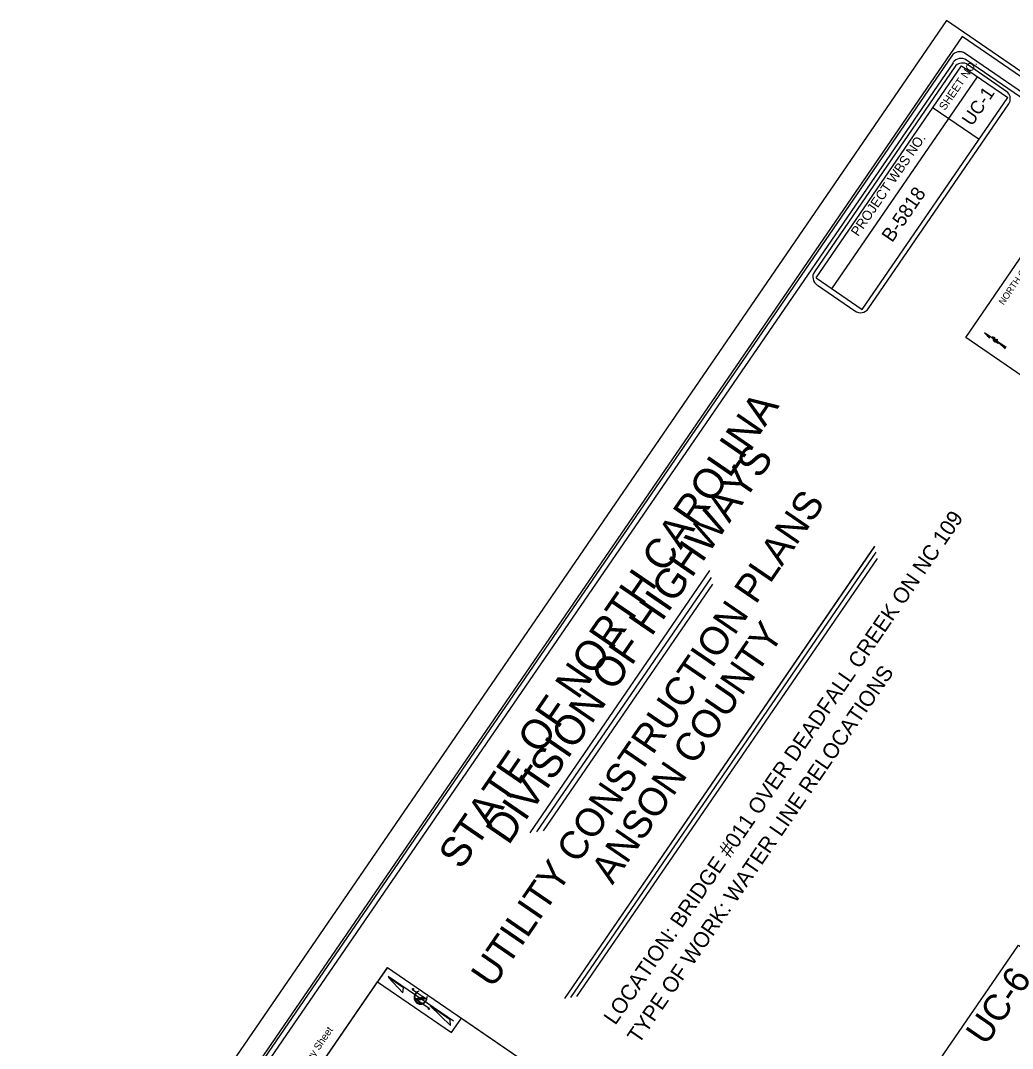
# Model space of a CAD drawing. Extents: x 1638787 to 1643250, y 391480 to 396306.
# Drawn here: x 1638787 to 1641236, y 393769 to 396306 of the extents above; entities that cross this region are included whole.
import ezdxf

# ---------------------------------------------------------------- set-up
doc = ezdxf.new("R2010")
doc.units = 0
for name, color, linetype in [('Old_Level_1', 7, 'Continuous'), ('Old_Level_32', 7, 'Continuous'), ('Old_Level_5', 7, 'Continuous'), ('Sheet North Arrow CELL', 7, 'Continuous'), ('Sheet Plan Layout CELL', 7, 'Continuous'), ('Sheet Plot Border Inside CELL', 7, 'Continuous'), ('Sheet Plot Border Outside CELL', 7, 'Continuous'), ('Sheet Title CELL', 7, 'Continuous'), ('UC Title Plan Sheet 34 CELL', 7, 'Continuous')]:
    doc.layers.add(name, color=color, linetype=linetype)

msp = doc.modelspace()

# ---------------------------------------------------------------- linework, layer by layer
at = {"layer": 'Old_Level_32'}
msp.add_line((1639692.9, 393968.5), (1639668.6, 393933), dxfattribs=at)
for points in [[(1639285.7, 393374.7), (1639692.9, 393968.5), (1640237.3, 393595.3), (1639830.1, 393001.5)], [(1639285.7, 393374.7), (1639668.6, 393933), (1639851, 393807.9), (1639875.3, 393843.4), (1640237.3, 393595.3), (1639830.1, 393001.5)]]:
    msp.add_lwpolyline(points, close=True, dxfattribs=at)
at = {"layer": 'Old_Level_5'}
for p, q in [((1641220.1, 395499.4), (1641166.8, 395535.9)), ((1641186.7, 395525.2), (1641197.7, 395517.7)), ((1641196, 395518.9), (1641189.1, 395517.6)), ((1641189.1, 395517.6), (1641200.2, 395510)), ((1641196.4, 395518.6), (1641189.5, 395517.3)), ((1641189.5, 395517.3), (1641190.5, 395516.6)), ((1641197.4, 395517.9), (1641190.5, 395516.6)), ((1641190.5, 395516.6), (1641197.4, 395517.9)), ((1641197.7, 395517.7), (1641190.8, 395516.4)), ((1641191.8, 395523.9), (1641191.9, 395523.9)), ((1641197.4, 395517.9), (1641196.4, 395518.6))]:
    msp.add_line(p, q, dxfattribs=at)
for points in [[(1641120.4, 395523.8), (1641374.9, 395894.9), (1641558.6, 395769), (1641304.1, 395397.8)], [(1641167, 395535.2), (1641178.8, 395522.7), (1641179.3, 395526.8)], [(1641201, 395511.8), (1641217.7, 395495.9), (1641217.4, 395500.6)]]:
    msp.add_lwpolyline(points, close=True, dxfattribs=at)
for centre in [(1641187, 395525.6), (1641199.9, 395509.5)]:
    msp.add_circle(centre, 0.527, dxfattribs=at)
for centre, radius, start, end in [((1641193.2, 395518.7), 5.43, 103.3997, 7.9538), ((1641193.5, 395519.1), 5.09, 108.6547, 4.1884)]:
    msp.add_arc(centre, radius, start, end, dxfattribs=at)
at = {"layer": 'Sheet North Arrow CELL'}
for p, q in [((1639855.8, 393836.3), (1639694.8, 393946.4)), ((1639755, 393914.1), (1639788, 393891.5)), ((1639770.4, 393910.3), (1639770.7, 393910.4)), ((1639782.9, 393895.1), (1639762.1, 393891.2)), ((1639762.1, 393891.2), (1639795.7, 393868.2)), ((1639784.1, 393894.2), (1639763.4, 393890.3)), ((1639763.4, 393890.3), (1639766.4, 393888.3)), ((1639787.1, 393892.2), (1639766.4, 393888.3)), ((1639766.4, 393888.3), (1639787.1, 393892.2)), ((1639788, 393891.5), (1639767.3, 393887.6)), ((1639787.1, 393892.2), (1639784.1, 393894.2))]:
    msp.add_line(p, q, dxfattribs=at)
for points in [[(1639695.5, 393944.3), (1639731, 393906.5), (1639732.6, 393918.9)], [(1639798.2, 393873.8), (1639848.7, 393825.9), (1639847.7, 393839.9)]]:
    msp.add_lwpolyline(points, close=True, dxfattribs=at)
for centre in [(1639755.9, 393915.4), (1639794.9, 393866.9)]:
    msp.add_circle(centre, 1.59, dxfattribs=at)
for centre, radius, start, end in [((1639774.5, 393894.4), 16.4, 103.4742, 8.0282), ((1639775.3, 393895.7), 15.4, 108.7292, 4.2629)]:
    msp.add_arc(centre, radius, start, end, dxfattribs=at)
at = {"layer": 'Sheet Plan Layout CELL'}
msp.add_lwpolyline([(1640975.6, 393623.7), (1641250.2, 394024.1), (1641596.6, 393786.6), (1641307.7, 393365.2)], close=True, dxfattribs=at)
at = {"layer": 'Sheet Plot Border Inside CELL'}
msp.add_lwpolyline([(1640937.7, 391536.4), (1643199.6, 394834.9), (1641111.3, 396267), (1638849.3, 392968.5)], close=True, dxfattribs=at)
at = {"layer": 'Sheet Plot Border Outside CELL'}
msp.add_lwpolyline([(1641072.9, 396306.4), (1638787.2, 392973.3), (1640964.4, 391480.2), (1643250.2, 394813.4)], close=True, dxfattribs=at)
at = {"layer": 'UC Title Plan Sheet 34 CELL'}
for p, q in [((1641093.3, 396192.2), (1640746.7, 395686.2)), ((1640750.8, 395671.4), (1641109.9, 396194.8)), ((1641109.9, 396194.8), (1641223.8, 396116.6)), ((1640790.1, 395644.1), (1641149.2, 396167.6)), ((1640864.7, 395593.1), (1641223.8, 396116.6)), ((1640879.6, 395594.8), (1641226.3, 396100.8)), ((1641039.9, 396090.9), (1641153.2, 396013.4)), ((1640750.8, 395671.4), (1640864.7, 395593.1)), ((1640754.1, 395653), (1640846.5, 395589.6)), ((1640130.6, 393892.2), (1640895.6, 395009)), ((1640130.6, 393892.2), (1640896.3, 395008.3)), ((1640145.8, 393894.5), (1640898.8, 394994)), ((1640160.4, 393897.1), (1640902.6, 394978.7)), ((1640044.8, 394300.8), (1640488.3, 394948.5)), ((1640061.4, 394303.4), (1640492.5, 394931.8)), ((1640077.9, 394306), (1640495.7, 394915.3))]:
    msp.add_line(p, q, dxfattribs=at)
for points in [[(1641085.8, 396219.1), (1639076.9, 393289.6)], [(1643157.8, 394827.3), (1641119.1, 396225.3)], [(1641088.9, 396202.4), (1639161.5, 393391.8)], [(1641224.5, 396129.2), (1641121.8, 396199.6)], [(1642775, 395075.2), (1641122.2, 396208.6)]]:
    msp.add_lwpolyline(points, dxfattribs=at)
for centre in [(1641105.4, 396205.6), (1641108.6, 396188.9)]:
    msp.add_arc(centre, 24, 55.5597, 145.5597, dxfattribs=at)
for centre, major_axis, ratio, start_param, end_param in [((1641113.7, 396178.2), (-20.3, 13.9), 0.926296, 4.933032, 6.283554), ((1641206.2, 396114.8), (20.3, -13.9), 0.941469, 0.000472, 1.282481), ((1640767, 395672.1), (-20.3, 13.9), 0.941469, 0.000468, 1.571265), ((1640859.5, 395608.8), (20.3, -13.9), 0.941469, 4.712857, 6.283654)]:
    msp.add_ellipse(centre, major_axis=major_axis, ratio=ratio, start_param=start_param, end_param=end_param, dxfattribs=at)

# ---------------------------------------------------------------- texts
at = {"layer": 'Old_Level_1'}
msp.add_text('UC-6', height=64.8, rotation=55.5597, dxfattribs=at).set_placement((1641170, 393773.4))
at = {"layer": 'Old_Level_5'}
msp.add_text('NORTH CAROLINA', height=16.198, rotation=55.5824, dxfattribs=at).set_placement((1641213.7, 395603))
at = {"layer": 'Sheet Title CELL'}
msp.add_text('See Sheet UC-2 For Standard Symbology Sheet', height=18, rotation=55.5597, dxfattribs=at).set_placement((1639266.8, 393387.7))
at = {"layer": 'UC Title Plan Sheet 34 CELL'}
for s, height, rotation, p in [('SHEET NO.', 19.8, 55.5882, (1641068.9, 396083.1)), ('UC-1', 32.67, 55.5882, (1641135.5, 396044)), ('PROJECT WBS NO.', 23.958, 55.5882, (1640854.8, 395771.9)), ('B-5818', 34.71, 55.5882, (1640938.7, 395756.7)), ('STATE OF NORTH CAROLINA', 73.734, 55.5882, (1639875.1, 394207.7)), ('DIVISION OF HIGHWAYS', 73.734, 55.5882, (1639991.7, 394268.5)), ('UTILITY CONSTRUCTION PLANS ', 69.676, 55.5882, (1639952.5, 393914.9)), ('LOCATION: BRIDGE #011 OVER DEADFALL CREEK ON NC 109', 38.266, 55.5455, (1640255.2, 393824.5)), ('ANSON COUNTY ', 69.676, 55.5882, (1640248.2, 394170.9)), ('TYPE OF WORK: WATER LINE RELOCATIONS', 38.266, 55.5455, (1640313.6, 393778.4))]:
    msp.add_text(s, height=height, rotation=rotation, dxfattribs=at).set_placement(p)

doc.saveas('drawing.dxf')
